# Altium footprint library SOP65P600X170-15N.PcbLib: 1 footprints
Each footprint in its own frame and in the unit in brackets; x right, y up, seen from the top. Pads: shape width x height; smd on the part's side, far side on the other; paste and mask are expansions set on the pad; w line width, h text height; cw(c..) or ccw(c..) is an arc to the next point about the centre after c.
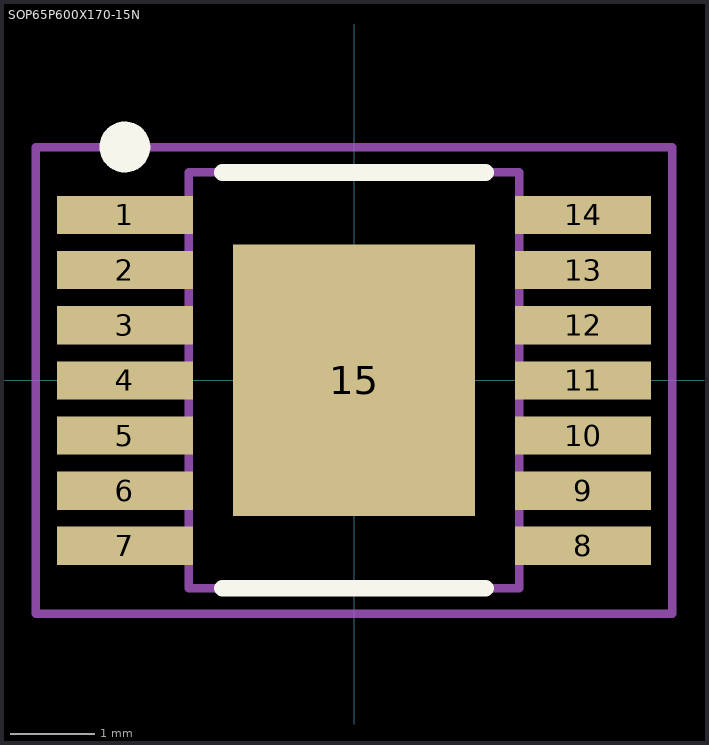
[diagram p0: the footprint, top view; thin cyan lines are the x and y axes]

## SOP65P600X170-15N [mm] "SOP,0.65mm pitch;14 pin,3.90mm W X 4.90mm L X 1.70mm H body (w/thermal tab)"
height 1.7
pads (15):
  rect 1.6x0.45 smd paste+0 mask+0: 1(-2.7,1.95) 2(-2.7,1.3) 3(-2.7,0.65) 4(-2.7,0) 5(-2.7,-0.65) 6(-2.7,-1.3) 7(-2.7,-1.95) 8(2.7,-1.95) 9(2.7,-1.3) 10(2.7,-0.65) 11(2.7,0) 12(2.7,0.65) 13(2.7,1.3) 14(2.7,1.95)
  rect 2.85x3.2 smd paste-0.555 mask+0: 15(0,0)
Top Overlay:
  circle w0.3: c-2.7,2.75 r0.15
  lines w0.2: -1.55,-2.45 1.55,-2.45 ; -1.55,2.45 1.55,2.45
Mechanical 3:
  text ".DESIGNATOR" at 0,0 h1.2
Mechanical 13:
  lines w0.1: -1.95,-2.45 1.95,-2.45 1.95,2.45 -1.95,2.45 -1.95,-2.45
Mechanical 15:
  lines w0.1: -0.5,0 0.5,0 ; 0,-0.5 0,0.5 ; -3.75,-2.75 -3.75,2.75 3.75,2.75 3.75,-2.75 -3.75,-2.75
3D body: height 1.71, standoff 0, extent -3,-2.45 3,2.45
